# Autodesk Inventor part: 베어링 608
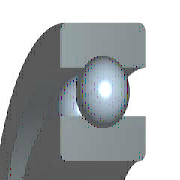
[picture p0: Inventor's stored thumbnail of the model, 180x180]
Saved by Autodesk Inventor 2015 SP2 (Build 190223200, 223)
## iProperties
IsCustomPart: 1
Created: 2009-02
Part Number: 베어링 608
Material: 강, 연강
Description: 깊은 그루브 볼 베어링
Document SubType Name: Modeling
Standard: KS B 2023
Designer: 한국산업디자인학원
Standards Organization: KS
Language: ko-KR
Size Designation: 608 - 8 x 22 x 7
Categories: <MemberInstance><Categories><Category DisplayName="샤프트 부품" InternalName="7f7aeb1f-a693-4053-b835-cee3144e0d98" Mnemonic="SHFT"><Category DisplayName="베어링" Inter
Density: 1 g/cm^3
Appearance: 강철
Author: 한국산업디자인학원
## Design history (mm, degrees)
sketch "스케치" dims "d0" = 3.64 (= -0.26 x WD + 0.26 x BD)
  geometry: L1 (1.68, 7.5)-(5.32, 7.5); L2 (3.5, 7.5)-(3.5, 5.68); L3 (3.5, 7.5)-(3.5, 9.32); L4 (2.148, 6.282)-(0, 6.282); L5 (0, 4)-(7, 4); L6 (2.148, 8.718)-(0, 8.718); L7 (0, 11)-(7, 11); L8 (7, 4)-(7, 6.282); L9 (4.852, 6.282)-(7, 6.282); L10 (4.852, 8.718)-(7, 8.718); L11 (7, 11)-(7, 8.718); L12 (-1.4, 0)-(8.4, 0) reference; L13 (0, -0.3)-(0, 5.3) reference
  constraints: 22 end point, 4 point on line, 2 collinear, 2 perpendicular, 2 symmetric about line, 1 midpoint, 1 parallel, 14 other
  dimensions: "d9" = 8 diameter of L5 L12 (= WD); "d11" = 22 diameter of L7 L12 (= BD); "d12" = 7 distance between parallel lines of L8 L13 (= KB); "d13" = 12.564 diameter of L9 L12 (= 0.326 x BD + 0.674 x WD)
revolve "본체" stored, may be unused: angle "d6" = 90 deg
revolve "볼" stored, may be unused: angle "d7" = 90 deg
pattern_circular "IDS_ARRAYBALL[SIMPL:T]" dims angle "d3" = 360 deg
body "Solid1"
fillet "모깎기1" dims "d1" = 0.3 (= KRS)
other parameters: "WD" = 8 [user parameter; used in 5 equation terms], "BD" = 22 [user parameter; used in 5 equation terms], "KB" = 7 [user parameter; used in 1 equation term], "KRS" = 0.3 [user parameter; used in 1 equation term], "d4" = 0, "d5" = 0, "d8" = 0, "d14" = 0, "d15" = 0, "BBA" = 0 [user parameter], "BC0" = 1370000 [user parameter], "BC" = 3250000 [user parameter], "BR" = 11 (= 0.5 x BD) [user parameter], "WR" = 4 (= 0.5 x WD) [user parameter]
